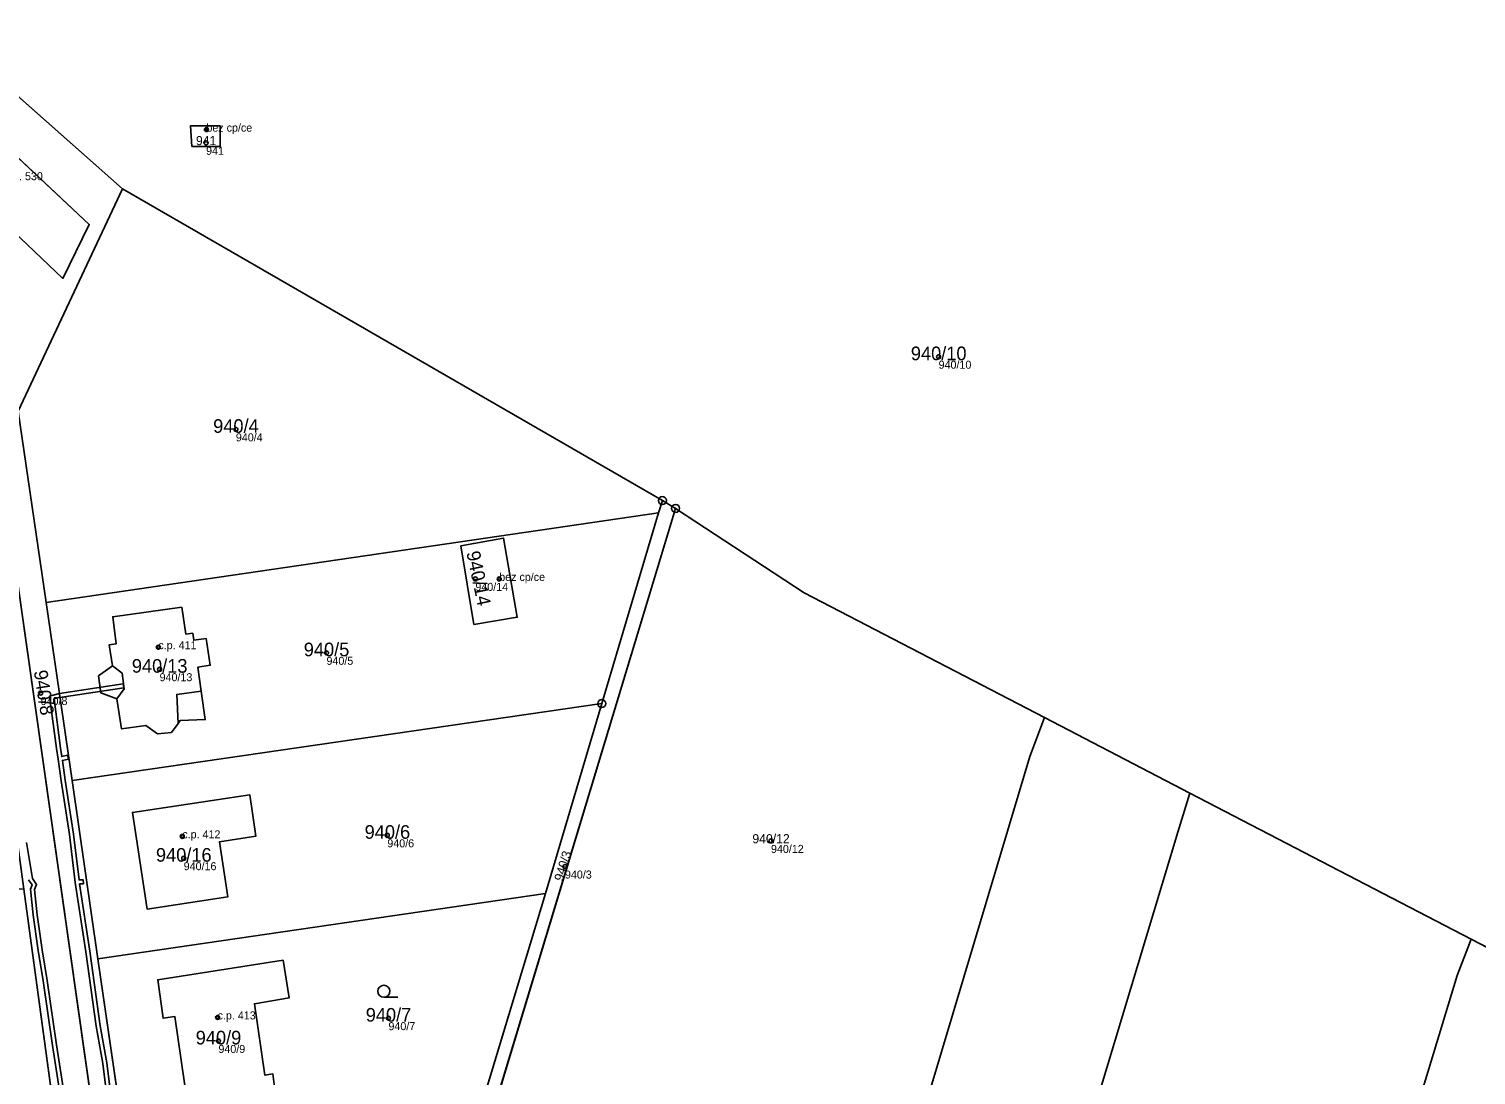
# Model space of a CAD drawing. Extents: x -603967 to -594699, y -1179315 to -1165625.
# Drawn here: x -597208.8 to -597028, y -1172664.1 to -1172533.5 of the extents above; entities that cross this region are included whole.
import ezdxf

# ---------------------------------------------------------------- set-up
doc = ezdxf.new("R2010")
doc.units = 0
for name, color, linetype in [('Definiční body', 7, 'Continuous'), ('Hranice parcel', 7, 'Continuous'), ('Parcelní čísla', 7, 'Continuous'), ('Polygon budovy', 7, 'Continuous'), ('Polygon parcely', 7, 'Continuous'), ('Vnitřní kresba', 7, 'Continuous'), ('Věcná břemena k části', 7, 'Continuous'), ('Značky bodu BP', 7, 'Continuous'), ('Značky budov', 7, 'Continuous'), ('Značky kultur', 7, 'Continuous')]:
    doc.layers.add(name, color=color, linetype=linetype)

msp = doc.modelspace()

# ---------------------------------------------------------------- linework, layer by layer
at = {"layer": 'Definiční body'}
for centre in [(-597186.59, -1172546.06994), (-597186.63, -1172547.71994), (-597095.12, -1172574.42994), (-597182.91, -1172583.49994), (-597152.99, -1172602.16994), (-597150.01, -1172602.16994), (-597192.59, -1172610.68994), (-597171.59, -1172611.39994), (-597192.44, -1172613.44994), (-597207.3, -1172616.41994), (-597189.6, -1172634.30994), (-597163.99, -1172634.18994), (-597116.06, -1172634.88994), (-597189.43, -1172637.04994), (-597141.8, -1172638.08994), (-597185.19, -1172656.91994), (-597163.85, -1172657.01994), (-597185.09, -1172659.86994)]:
    msp.add_circle(centre, 0.25, dxfattribs=at)
at = {"layer": 'Hranice parcel'}
for p, q in [((-597218.04, -1172534.94), (-597197.09, -1172553.45)), ((-597197.09, -1172553.45), (-597210.1, -1172581.2)), ((-597197.09, -1172553.45), (-597129.63, -1172592.38)), ((-597206.62, -1172605.09), (-597210.1, -1172581.2)), ((-597200.46, -1172670.98), (-597212.52, -1172586.36)), ((-597129.63, -1172592.38), (-597130.13, -1172593.91)), ((-597129.63, -1172592.38), (-597127.98, -1172593.36)), ((-597206.62, -1172605.09), (-597130.13, -1172593.91)), ((-597127.98, -1172593.36), (-597150.95, -1172669.23)), ((-597130.13, -1172593.91), (-597137.2, -1172617.74)), ((-597203.38, -1172627.35), (-597206.62, -1172605.09)), ((-597203.38, -1172627.35), (-597137.2, -1172617.74)), ((-597137.2, -1172617.74), (-597144.25, -1172641.45)), ((-597081.9, -1172619.48), (-597063.74, -1172628.93)), ((-597200.14, -1172649.62), (-597203.38, -1172627.35)), ((-597063.74, -1172628.93), (-597028.61, -1172647.14)), ((-597205.28, -1172671.19), (-597209.4, -1172640.92)), ((-597144.25, -1172641.45), (-597200.14, -1172649.62)), ((-597152.68, -1172669.43), (-597144.25, -1172641.45)), ((-597028.61, -1172647.14), (-597018, -1172652.66)), ((-597200.14, -1172649.62), (-597197.06, -1172670.81))]:
    msp.add_line(p, q, dxfattribs=at)
for points in [[(-597188.41, -1172548.16), (-597188.58, -1172545.6), (-597184.86, -1172545.6), (-597184.86, -1172548.16), (-597188.41, -1172548.16)], [(-597127.98, -1172593.36), (-597111.9, -1172603.92), (-597081.9, -1172619.48)], [(-597149.47, -1172597.07), (-597147.76, -1172606.96), (-597153.17, -1172607.84), (-597154.81, -1172598.05), (-597149.47, -1172597.07)], [(-597188.3, -1172608.94), (-597188.17, -1172609.83), (-597186.61, -1172609.61), (-597186.12, -1172612.94), (-597187.66, -1172613.17), (-597187.25, -1172616.18), (-597186.74, -1172619.74), (-597189.87, -1172619.86), (-597190.11, -1172620.2), (-597190.96, -1172621.33), (-597192.69, -1172621.53), (-597194.15, -1172620.45), (-597197.2, -1172620.88), (-597197.78, -1172617.13), (-597199.79, -1172616.38), (-597200.06, -1172614.28), (-597198.34, -1172613.03), (-597198.73, -1172610.38), (-597197.85, -1172610.26), (-597198.29, -1172606.9), (-597189.67, -1172605.7), (-597189.18, -1172609.06), (-597188.3, -1172608.94)], [(-597096.1, -1172665.68), (-597083.72, -1172624.35), (-597081.9, -1172619.48)], [(-597195.83, -1172631.33), (-597181.18, -1172629.12), (-597180.43, -1172634.3), (-597184.97, -1172634.98), (-597183.93, -1172641.88), (-597194.01, -1172643.39), (-597195.83, -1172631.33)], [(-597145.17, -1172899.03), (-597065.25, -1172633.8), (-597063.74, -1172628.93)], [(-597092.38, -1172856.05), (-597030.34, -1172651.68), (-597028.61, -1172647.14)], [(-597178.28, -1172663.97), (-597178, -1172666.31), (-597178.97, -1172666.45), (-597178.67, -1172668.29), (-597184.62, -1172669.25), (-597184.8, -1172668.16), (-597185.96, -1172668.35), (-597186.1, -1172667.3), (-597188.94, -1172667.7), (-597190.53, -1172656.81), (-597192.01, -1172657.03), (-597192.68, -1172652.21), (-597177.02, -1172649.78), (-597176.25, -1172654.47), (-597180.6, -1172655.22), (-597179.28, -1172664.15), (-597178.28, -1172663.97)]]:
    msp.add_lwpolyline(points, dxfattribs=at)
at = {"layer": 'Polygon budovy'}
for points in [[(-597220.78, -1172542.45), (-597225.15, -1172547.16), (-597216.41, -1172555.25), (-597219.42, -1172558.44), (-597215.53, -1172562.12), (-597211.62, -1172557.91), (-597204.51, -1172564.65), (-597201.22, -1172557.91), (-597215.95, -1172544.14), (-597217.34, -1172545.68)], [(-597188.58, -1172545.6), (-597188.41, -1172548.16), (-597184.86, -1172548.16), (-597184.86, -1172545.6)], [(-597154.81, -1172598.05), (-597153.17, -1172607.84), (-597147.76, -1172606.96), (-597149.47, -1172597.07)], [(-597197.2, -1172620.88), (-597194.15, -1172620.45), (-597192.69, -1172621.53), (-597190.96, -1172621.33), (-597190.11, -1172620.2), (-597190.3, -1172616.58), (-597187.25, -1172616.18), (-597187.66, -1172613.17), (-597186.12, -1172612.94), (-597186.61, -1172609.61), (-597188.17, -1172609.83), (-597188.3, -1172608.94), (-597189.18, -1172609.06), (-597189.67, -1172605.7), (-597198.29, -1172606.9), (-597197.85, -1172610.26), (-597198.73, -1172610.38), (-597198.34, -1172613.03), (-597197.12, -1172613.94), (-597196.88, -1172615.89), (-597197.78, -1172617.13)], [(-597183.93, -1172641.88), (-597184.97, -1172634.98), (-597180.43, -1172634.3), (-597181.18, -1172629.12), (-597195.83, -1172631.33), (-597194.01, -1172643.39)], [(-597180.6, -1172655.22), (-597176.25, -1172654.47), (-597177.02, -1172649.78), (-597192.68, -1172652.21), (-597192.01, -1172657.03), (-597190.53, -1172656.81), (-597188.94, -1172667.7), (-597186.1, -1172667.3), (-597185.96, -1172668.35), (-597184.8, -1172668.16), (-597184.62, -1172669.25), (-597178.67, -1172668.29), (-597178.97, -1172666.45), (-597178, -1172666.31), (-597178.28, -1172663.97), (-597179.28, -1172664.15)]]:
    msp.add_lwpolyline(points, close=True, dxfattribs=at)
at = {"layer": 'Polygon parcely'}
for points in [[(-597230.58, -1172397.86), (-597225.66, -1172519.43), (-597370.04, -1172389.55), (-597371.62, -1172396.88), (-597322.85, -1172441.5), (-597295.24, -1172466.75), (-597267.51, -1172491.25), (-597242.77, -1172513.09), (-597218.04, -1172534.94), (-597197.09, -1172553.45), (-597129.63, -1172592.38), (-597127.98, -1172593.36), (-597111.9, -1172603.92), (-597081.9, -1172619.48), (-597063.74, -1172628.93), (-597028.61, -1172647.14), (-597018, -1172652.66), (-597016.16, -1172524.9), (-597116.51, -1172532.05), (-597117.85, -1172513.57), (-597182.62, -1172520.24), (-597187.57, -1172402.48), (-597194.03, -1172394.46), (-597229.74, -1172397.83)], [(-597218.04, -1172534.94), (-597240.05, -1172558.29), (-597232.94, -1172564.92), (-597232.69, -1172566.42), (-597228.72, -1172570.29), (-597222.41, -1172575.2), (-597218.02, -1172577.53), (-597210.1, -1172581.2), (-597197.09, -1172553.45)], [(-597188.41, -1172548.16), (-597188.58, -1172545.6), (-597184.86, -1172545.6), (-597184.86, -1172548.16)], [(-597188.41, -1172548.16), (-597184.86, -1172548.16), (-597184.86, -1172545.6), (-597188.58, -1172545.6)], [(-597206.62, -1172605.09), (-597130.13, -1172593.91), (-597129.63, -1172592.38), (-597197.09, -1172553.45), (-597210.1, -1172581.2)], [(-597206.62, -1172605.09), (-597210.1, -1172581.2), (-597212.52, -1172586.36), (-597200.46, -1172670.98), (-597197.06, -1172670.81), (-597200.14, -1172649.62), (-597203.38, -1172627.35)], [(-597200.39, -1172674.62), (-597200.46, -1172670.98), (-597212.52, -1172586.36), (-597214.45, -1172590.49), (-597216.82, -1172590.41), (-597215.81, -1172593.92), (-597212.67, -1172616.94), (-597209.4, -1172640.92), (-597205.28, -1172671.19), (-597204.91, -1172674.99), (-597204.13, -1172680.6), (-597201.71, -1172697.9), (-597199.52, -1172712.29), (-597197.72, -1172725.66), (-597195.27, -1172739.28), (-597192.33, -1172756.74), (-597187.54, -1172781.71), (-597186.69, -1172787.77), (-597184.18, -1172779.24), (-597184.59, -1172776.79)], [(-597144.25, -1172641.45), (-597152.68, -1172669.43), (-597184.59, -1172776.79), (-597184.18, -1172779.24), (-597151.89, -1172672.35), (-597150.95, -1172669.23), (-597127.98, -1172593.36), (-597129.63, -1172592.38), (-597130.13, -1172593.91), (-597137.2, -1172617.74)], [(-597137.2, -1172617.74), (-597130.13, -1172593.91), (-597206.62, -1172605.09), (-597203.38, -1172627.35)], [(-597081.9, -1172619.48), (-597111.9, -1172603.92), (-597127.98, -1172593.36), (-597150.95, -1172669.23), (-597096.1, -1172665.68), (-597083.72, -1172624.35)], [(-597149.47, -1172597.07), (-597154.81, -1172598.05), (-597153.17, -1172607.84), (-597147.76, -1172606.96)], [(-597149.47, -1172597.07), (-597147.76, -1172606.96), (-597153.17, -1172607.84), (-597154.81, -1172598.05)], [(-597188.3, -1172608.94), (-597189.18, -1172609.06), (-597189.67, -1172605.7), (-597198.29, -1172606.9), (-597197.85, -1172610.26), (-597198.73, -1172610.38), (-597198.34, -1172613.03), (-597200.06, -1172614.28), (-597199.79, -1172616.38), (-597197.78, -1172617.13), (-597197.2, -1172620.88), (-597194.15, -1172620.45), (-597192.69, -1172621.53), (-597190.96, -1172621.33), (-597190.11, -1172620.2), (-597189.87, -1172619.86), (-597186.74, -1172619.74), (-597187.25, -1172616.18), (-597187.66, -1172613.17), (-597186.12, -1172612.94), (-597186.61, -1172609.61), (-597188.17, -1172609.83)], [(-597188.3, -1172608.94), (-597188.17, -1172609.83), (-597186.61, -1172609.61), (-597186.12, -1172612.94), (-597187.66, -1172613.17), (-597187.25, -1172616.18), (-597186.74, -1172619.74), (-597189.87, -1172619.86), (-597190.11, -1172620.2), (-597190.96, -1172621.33), (-597192.69, -1172621.53), (-597194.15, -1172620.45), (-597197.2, -1172620.88), (-597197.78, -1172617.13), (-597199.79, -1172616.38), (-597200.06, -1172614.28), (-597198.34, -1172613.03), (-597198.73, -1172610.38), (-597197.85, -1172610.26), (-597198.29, -1172606.9), (-597189.67, -1172605.7), (-597189.18, -1172609.06)], [(-597203.38, -1172627.35), (-597200.14, -1172649.62), (-597144.25, -1172641.45), (-597137.2, -1172617.74)], [(-597065.25, -1172633.8), (-597063.74, -1172628.93), (-597081.9, -1172619.48), (-597083.72, -1172624.35), (-597096.1, -1172665.68), (-597097.09, -1172668.97), (-597157.76, -1172871.57), (-597146.71, -1172896.69), (-597145.17, -1172899.03)], [(-597195.83, -1172631.33), (-597194.01, -1172643.39), (-597183.93, -1172641.88), (-597184.97, -1172634.98), (-597180.43, -1172634.3), (-597181.18, -1172629.12)], [(-597195.83, -1172631.33), (-597181.18, -1172629.12), (-597180.43, -1172634.3), (-597184.97, -1172634.98), (-597183.93, -1172641.88), (-597194.01, -1172643.39)], [(-597136.59, -1172910.65), (-597113.34, -1172923.26), (-597092.38, -1172856.05), (-597030.34, -1172651.68), (-597028.61, -1172647.14), (-597063.74, -1172628.93), (-597065.25, -1172633.8), (-597145.17, -1172899.03), (-597139.09, -1172908.23)], [(-597236.13, -1172659.19), (-597236.69, -1172667.61), (-597236.95, -1172671.49), (-597208.27, -1172671.22), (-597205.28, -1172671.19), (-597209.4, -1172640.92), (-597217.48, -1172640.31), (-597234.85, -1172639.05), (-597235.18, -1172644.1), (-597235.6, -1172650.79)], [(-597200.14, -1172649.62), (-597197.06, -1172670.81), (-597152.68, -1172669.43), (-597144.25, -1172641.45)], [(-597092.38, -1172856.05), (-597067.24, -1172865.47), (-597061.58, -1172854.05), (-597053.2, -1172845.48), (-597044.5, -1172837.85), (-597034.57, -1172832.87), (-597031.45, -1172831.97), (-596981.74, -1172664.88), (-596992.13, -1172661.39), (-597018, -1172652.66), (-597028.61, -1172647.14), (-597030.34, -1172651.68)], [(-597178.28, -1172663.97), (-597179.28, -1172664.15), (-597180.6, -1172655.22), (-597176.25, -1172654.47), (-597177.02, -1172649.78), (-597192.68, -1172652.21), (-597192.01, -1172657.03), (-597190.53, -1172656.81), (-597188.94, -1172667.7), (-597186.1, -1172667.3), (-597185.96, -1172668.35), (-597184.8, -1172668.16), (-597184.62, -1172669.25), (-597178.67, -1172668.29), (-597178.97, -1172666.45), (-597178, -1172666.31)], [(-597178.28, -1172663.97), (-597178, -1172666.31), (-597178.97, -1172666.45), (-597178.67, -1172668.29), (-597184.62, -1172669.25), (-597184.8, -1172668.16), (-597185.96, -1172668.35), (-597186.1, -1172667.3), (-597188.94, -1172667.7), (-597190.53, -1172656.81), (-597192.01, -1172657.03), (-597192.68, -1172652.21), (-597177.02, -1172649.78), (-597176.25, -1172654.47), (-597180.6, -1172655.22), (-597179.28, -1172664.15)]]:
    msp.add_lwpolyline(points, close=True, dxfattribs=at)
at = {"layer": 'Vnitřní kresba'}
for p, q in [((-597215.95, -1172544.14), (-597201.22, -1172557.91)), ((-597204.51, -1172564.65), (-597211.62, -1172557.91)), ((-597201.22, -1172557.91), (-597204.51, -1172564.65)), ((-597198.34, -1172613.03), (-597197.12, -1172613.94)), ((-597197.12, -1172613.94), (-597196.88, -1172615.89)), ((-597196.88, -1172615.89), (-597197.78, -1172617.13)), ((-597190.3, -1172616.58), (-597187.25, -1172616.18)), ((-597190.11, -1172620.2), (-597190.3, -1172616.58))]:
    msp.add_line(p, q, dxfattribs=at)
at = {"layer": 'Věcná břemena k části'}
msp.add_lwpolyline([(-597196.98, -1172615.26), (-597204.96, -1172616.49), (-597204.89, -1172616.97), (-597196.9, -1172615.76)], close=True, dxfattribs=at)
for points in [[(-597198.29, -1172668.61), (-597199.04, -1172662.58), (-597199.85, -1172657.95), (-597201.17, -1172648.63), (-597202.43, -1172640.26), (-597201.96, -1172640.22), (-597202, -1172639.72), (-597202.5, -1172639.76), (-597203.21, -1172634.02), (-597204.23, -1172627.28), (-597204.59, -1172624.83), (-597203.83, -1172624.66), (-597203.93, -1172624.18), (-597204.66, -1172624.34), (-597204.8, -1172623.28), (-597205.62, -1172617.16), (-597205.01, -1172616.99), (-597204.89, -1172616.97), (-597204.96, -1172616.49), (-597205.11, -1172616.51), (-597206.18, -1172616.8), (-597205.3, -1172623.34), (-597205.12, -1172624.67), (-597204.73, -1172627.36), (-597203.71, -1172634.08), (-597202.97, -1172640.06), (-597201.67, -1172648.71), (-597200.35, -1172658.03), (-597199.54, -1172662.66), (-597198.79, -1172668.69)], [(-597203.99, -1172668.92), (-597205.31, -1172660.36), (-597206.48, -1172652.29), (-597207.11, -1172648.49), (-597207.73, -1172644.1), (-597208.06, -1172640.96), (-597207.81, -1172640.31), (-597208.33, -1172639.56), (-597209.06, -1172635.06)], [(-597208.81, -1172639.76), (-597208.37, -1172640.37), (-597208.58, -1172640.9), (-597208.23, -1172644.16), (-597207.61, -1172648.57), (-597206.98, -1172652.37), (-597205.81, -1172660.44), (-597204.49, -1172669)]]:
    msp.add_lwpolyline(points, dxfattribs=at)
at = {"layer": 'Značky bodu BP'}
for centre, radius in [((-597129.63, -1172592.37988), 0.5), ((-597129.63, -1172592.37988), 0.0303), ((-597127.98, -1172593.35988), 0.5), ((-597127.98, -1172593.35988), 0.0303), ((-597137.2, -1172617.73988), 0.5), ((-597137.2, -1172617.73988), 0.0303)]:
    msp.add_circle(centre, radius, dxfattribs=at)
at = {"layer": 'Značky budov'}
for centre, radius in [((-597186.59456, -1172546.06944), 0.11725), ((-597150.0168, -1172602.16916), 0.175), ((-597192.5968, -1172610.68916), 0.175), ((-597189.6068, -1172634.30916), 0.175), ((-597185.1968, -1172656.91916), 0.175)]:
    msp.add_circle(centre, radius, dxfattribs=at)
at = {"layer": 'Značky kultur'}
msp.add_line((-597164.423, -1172654.41), (-597162.673, -1172654.41), dxfattribs=at)
msp.add_circle((-597164.42286, -1172653.65981), 0.75, dxfattribs=at)

# ---------------------------------------------------------------- texts
at = {"layer": 'Definiční body'}
for s, p in [('bez cp/ce', (-597186.59, -1172546.32)), ('941', (-597186.63, -1172549.209)), ('c.p. 530', (-597211.78, -1172552.38)), ('940/10', (-597095.12, -1172575.919)), ('940/4', (-597182.91, -1172584.989)), ('bez cp/ce', (-597150.01, -1172602.42)), ('940/14', (-597152.99, -1172603.659)), ('c.p. 411', (-597192.59, -1172610.94)), ('940/5', (-597171.59, -1172612.889)), ('940/13', (-597192.44, -1172614.939)), ('940/8', (-597207.3, -1172617.909)), ('c.p. 412', (-597189.6, -1172634.56)), ('940/6', (-597163.99, -1172635.679)), ('940/12', (-597116.06, -1172636.379)), ('940/16', (-597189.43, -1172638.539)), ('940/3', (-597141.8, -1172639.579)), ('c.p. 413', (-597185.19, -1172657.17)), ('940/7', (-597163.85, -1172658.509)), ('940/9', (-597185.09, -1172661.359))]:
    msp.add_text(s, height=0.999996, dxfattribs=at).set_placement(p)
at = {"layer": 'Parcelní čísla'}
for s, height, p in [('941', 1.14, (-597187.898, -1172548.005)), ('940/10', 1.699998, (-597098.586, -1172574.855)), ('940/4', 1.699998, (-597185.746, -1172583.925)), ('940/5', 1.699998, (-597174.426, -1172611.825)), ('940/13', 1.699998, (-597195.906, -1172613.875)), ('940/6', 1.699998, (-597166.826, -1172634.615)), ('940/12', 1.14, (-597118.384, -1172635.175)), ('940/16', 1.699998, (-597192.896, -1172637.475)), ('940/7', 1.699998, (-597166.686, -1172657.445)), ('940/9', 1.699998, (-597187.926, -1172660.295))]:
    msp.add_text(s, height=height, dxfattribs=at).set_placement(p)
for s, height, rotation, p in [('940/14', 1.699998, 282, (-597154.126, -1172598.867)), ('940/8', 1.699998, 279, (-597208.163, -1172613.685)), ('940/3', 1.14, 73, (-597142.083, -1172639.992))]:
    msp.add_text(s, height=height, rotation=rotation, dxfattribs=at).set_placement(p)

doc.saveas('drawing.dxf')
